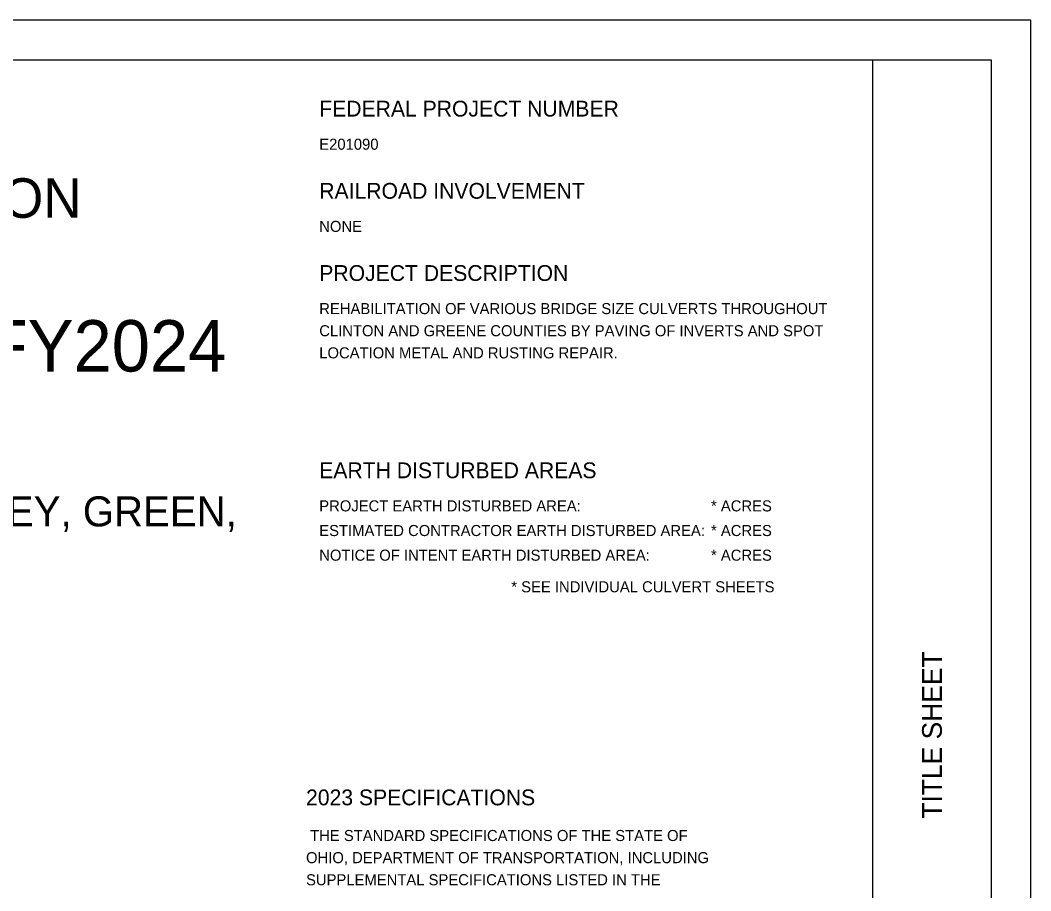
# Model space of a CAD drawing. Extents: x 43.1 to 77.1, y 2.7 to 24.7.
# Drawn here: x 64.35 to 77.13, y 13.64 to 24.66 of the extents above; entities that cross this region are included whole.
import ezdxf

# ---------------------------------------------------------------- set-up
doc = ezdxf.new("R2010")
doc.units = 0
for name, color, linetype in [('SH_Border', 7, 'Continuous'), ('SH_Cut_Line', 7, 'Continuous'), ('SH_Data', 7, 'Continuous'), ('SH_Text', 7, 'Continuous')]:
    doc.layers.add(name, color=color, linetype=linetype)

msp = doc.modelspace()

# ---------------------------------------------------------------- linework, layer by layer
at = {"layer": 'SH_Border'}
msp.add_line((75.131, 3.158), (75.131, 24.158), dxfattribs=at)
msp.add_lwpolyline([(44.631, 24.158), (76.631, 24.158), (76.631, 3.158), (44.631, 3.158)], close=True, dxfattribs=at)
at = {"layer": 'SH_Cut_Line'}
msp.add_lwpolyline([(43.131, 2.658), (77.131, 2.658), (77.131, 24.658), (43.131, 24.658)], close=True, dxfattribs=at)

# ---------------------------------------------------------------- texts
at = {"layer": 'SH_Data'}
msp.add_text('TITLE SHEET', height=0.25, rotation=90, dxfattribs=at).set_placement((76.006, 14.555))
at = {"layer": 'SH_Text'}
for s, height, p in [('FEDERAL PROJECT NUMBER', 0.2, (68.131, 23.439)), ('E201090', 0.14, (68.131, 23.019)), ('DEPARTMENT OF TRANSPORTATION', 0.5, (53.051, 22.158)), ('RAILROAD INVOLVEMENT', 0.2, (68.131, 22.399)), ('NONE', 0.14, (68.131, 21.979)), ('PROJECT DESCRIPTION', 0.2, (68.131, 21.359)), ('REHABILITATION OF VARIOUS BRIDGE SIZE CULVERTS THROUGHOUT ', 0.14, (68.131, 20.939)), ('CLI/GRE CULVERT REPAIR FY2024', 0.65, (52.417, 20.213)), ('CLINTON AND GREENE COUNTIES BY PAVING OF INVERTS AND SPOT ', 0.14, (68.131, 20.659)), ('LOCATION METAL AND RUSTING REPAIR.', 0.14, (68.131, 20.379)), ('EARTH DISTURBED AREAS', 0.2, (68.131, 18.863)), ('CITY OF BEAVER CREEK, XENIA, SPRING VALLEY, GREEN,', 0.38, (52.659, 18.253)), ('PROJECT EARTH DISTURBED AREA:', 0.14, (68.131, 18.443)), ('* ACRES', 0.14, (73.086, 18.443)), ('ESTIMATED CONTRACTOR EARTH DISTURBED AREA:', 0.14, (68.131, 18.131)), ('* ACRES', 0.14, (73.086, 18.131)), ('NOTICE OF INTENT EARTH DISTURBED AREA:', 0.14, (68.131, 17.819)), ('* ACRES', 0.14, (73.086, 17.819)), ('* SEE INDIVIDUAL CULVERT SHEETS', 0.14, (70.56, 17.419)), ('2023 SPECIFICATIONS', 0.2, (67.964, 14.724)), (' THE STANDARD SPECIFICATIONS OF THE STATE OF', 0.14, (67.964, 14.272)), ('OHIO, DEPARTMENT OF TRANSPORTATION, INCLUDING', 0.14, (67.964, 13.992)), ('SUPPLEMENTAL SPECIFICATIONS LISTED IN THE', 0.14, (67.964, 13.712))]:
    msp.add_text(s, height=height, dxfattribs=at).set_placement(p)

doc.saveas('drawing.dxf')
